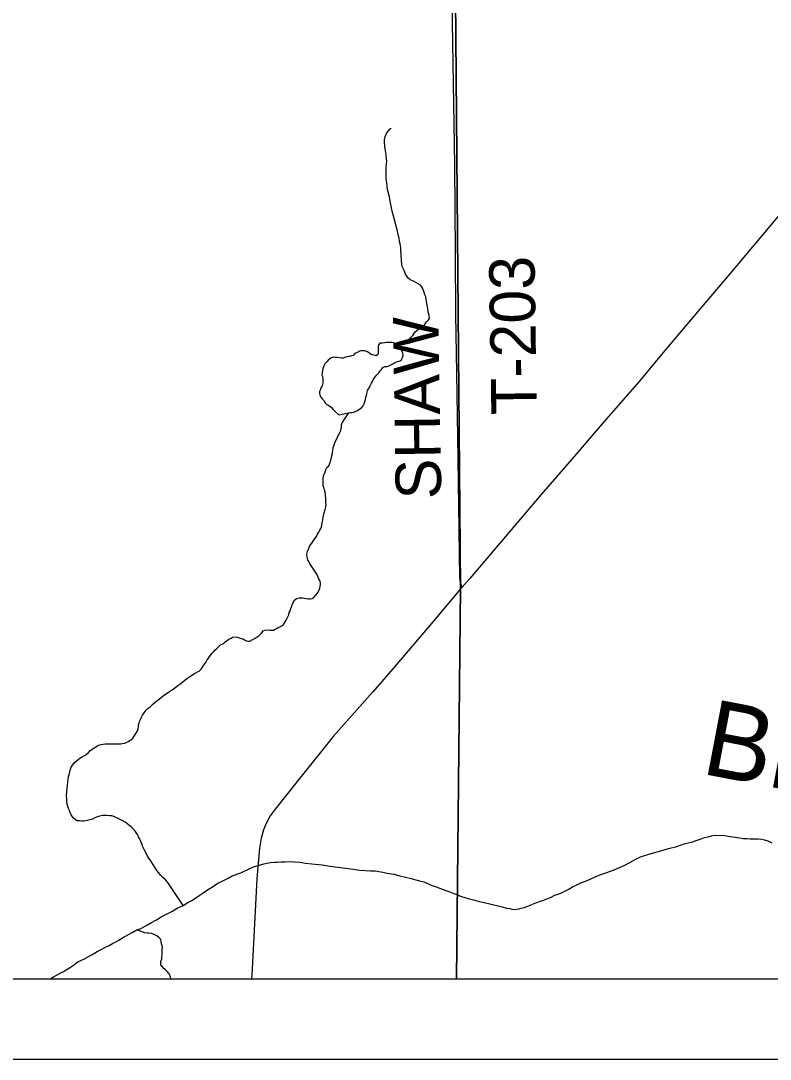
# Model space of a CAD drawing. Extents: x 0 to 34, y 0 to 22.
# Drawn here: x 3.905 to 4.841, y 14.238 to 15.535 of the extents above; entities that cross this region are included whole.
import ezdxf

# ---------------------------------------------------------------- set-up
doc = ezdxf.new("R2010")
doc.units = 0
for name, color, linetype in [('GM_X_County', 7, 'Continuous'), ('GM_X_Minor_Lake', 7, 'Continuous'), ('GM_X_Minor_River', 7, 'Continuous'), ('GM_X_Minor_River_Text', 7, 'Continuous'), ('GM_X_Township', 7, 'Continuous'), ('GM_X_Township_Road', 7, 'Continuous'), ('GM_X_Township_Road_Text', 7, 'Continuous'), ('SH_Data', 7, 'Continuous')]:
    doc.layers.add(name, color=color, linetype=linetype)

msp = doc.modelspace()

# ---------------------------------------------------------------- linework, layer by layer
at = {"layer": 'GM_X_County'}
msp.add_lwpolyline([(9.1622, 14.342), (9.1622, 21.1385), (2.3622, 21.1385), (2.3622, 14.3385), (9.0003, 14.3385)], dxfattribs=at)
at = {"layer": 'GM_X_Minor_Lake'}
for points in [[(4.3369, 15.0668), (4.3372, 15.0691), (4.3375, 15.0714), (4.3382, 15.0733), (4.3393, 15.0752), (4.3404, 15.0771), (4.3415, 15.0791), (4.3433, 15.0825), (4.3444, 15.0845), (4.3452, 15.0864), (4.347, 15.0891), (4.3492, 15.0922), (4.3522, 15.0953), (4.354, 15.0976), (4.3555, 15.0996), (4.357, 15.1015), (4.3596, 15.1031), (4.3623, 15.1031), (4.3645, 15.1036), (4.3672, 15.1051), (4.3706, 15.1071), (4.3732, 15.1087), (4.3762, 15.1095), (4.38, 15.1108), (4.3811, 15.1127), (4.3818, 15.1146), (4.3825, 15.1173), (4.3824, 15.12), (4.3816, 15.1218), (4.3808, 15.1241), (4.3796, 15.1267), (4.3776, 15.1297), (4.3757, 15.1308), (4.373, 15.1319), (4.3707, 15.1326), (4.3684, 15.133), (4.3658, 15.1333), (4.3639, 15.1332), (4.3616, 15.1332), (4.3597, 15.1328), (4.3567, 15.1323), (4.3536, 15.1322), (4.3518, 15.1303), (4.3514, 15.128), (4.3515, 15.1253), (4.3515, 15.1231), (4.3516, 15.1208), (4.3509, 15.1181), (4.349, 15.1165), (4.3463, 15.1172), (4.3441, 15.1176), (4.3421, 15.1187), (4.3394, 15.1205), (4.3371, 15.122), (4.3348, 15.1227), (4.3325, 15.1226), (4.3299, 15.1229), (4.328, 15.1225), (4.325, 15.1209), (4.3223, 15.1193), (4.3201, 15.117), (4.3182, 15.1166), (4.3156, 15.1158), (4.3129, 15.1153), (4.3106, 15.1149), (4.3076, 15.1137), (4.3057, 15.1136), (4.3027, 15.1139), (4.3, 15.1146), (4.2973, 15.1146), (4.295, 15.1149), (4.2928, 15.1141), (4.289, 15.1113), (4.2876, 15.1094), (4.2849, 15.1067), (4.2835, 15.104), (4.2824, 15.1005), (4.2817, 15.0986), (4.2814, 15.0956), (4.2811, 15.0925), (4.2819, 15.0906), (4.2823, 15.088), (4.2824, 15.0842), (4.2821, 15.0823), (4.2814, 15.0792), (4.2803, 15.0773), (4.2792, 15.0746), (4.2781, 15.0719), (4.2782, 15.07), (4.2786, 15.0674), (4.2802, 15.0647), (4.2814, 15.0628), (4.2837, 15.0606), (4.2853, 15.058), (4.2873, 15.0558), (4.2896, 15.0547), (4.2927, 15.0525), (4.2946, 15.0498), (4.2977, 15.0469), (4.3024, 15.0428), (4.3149, 15.0454)], [(4.3149, 15.0454), (4.3168, 15.0458), (4.3187, 15.0458), (4.321, 15.0463), (4.3228, 15.0471), (4.3255, 15.0483), (4.3285, 15.0502), (4.3307, 15.0518), (4.3326, 15.0541), (4.334, 15.0568), (4.3354, 15.0622), (4.3361, 15.0649), (4.3369, 15.0668)]]:
    msp.add_lwpolyline(points, dxfattribs=at)
at = {"layer": 'GM_X_Minor_River'}
for points in [[(4.3776, 15.1297), (4.3912, 15.138), (4.393, 15.1404), (4.3949, 15.1419), (4.3974, 15.1462), (4.3997, 15.1481), (4.4027, 15.1505), (4.4045, 15.152), (4.4072, 15.1536), (4.4101, 15.1567), (4.412, 15.1591), (4.4142, 15.1614), (4.4157, 15.1637), (4.4152, 15.1671), (4.4144, 15.1698), (4.414, 15.172), (4.4135, 15.1747), (4.4131, 15.1781), (4.4122, 15.1819), (4.4118, 15.1846), (4.4114, 15.1864), (4.4109, 15.1902), (4.4097, 15.1925), (4.4089, 15.1955), (4.408, 15.1982), (4.4068, 15.2012), (4.4056, 15.2031), (4.4045, 15.2049), (4.3956, 15.2097), (4.3933, 15.2108), (4.3914, 15.2115), (4.3887, 15.2141), (4.3871, 15.2159), (4.3855, 15.2186), (4.3843, 15.2224), (4.3827, 15.2257), (4.3815, 15.228), (4.381, 15.2314), (4.3806, 15.2344), (4.3805, 15.2375), (4.3801, 15.2405), (4.38, 15.2439), (4.3799, 15.247), (4.3799, 15.2489), (4.3798, 15.2512), (4.3794, 15.2538), (4.3789, 15.2565), (4.3781, 15.2595), (4.3776, 15.2633), (4.3764, 15.2678), (4.3755, 15.2724), (4.3734, 15.2799), (4.3714, 15.2879), (4.3689, 15.297), (4.3672, 15.3053), (4.3663, 15.3098), (4.3654, 15.3151), (4.3642, 15.3197), (4.3633, 15.3242), (4.3628, 15.3284), (4.3624, 15.3326), (4.3615, 15.3375), (4.3613, 15.3432), (4.3616, 15.3482), (4.3615, 15.352), (4.3618, 15.3558), (4.3621, 15.3596), (4.362, 15.3626), (4.3616, 15.3664), (4.3615, 15.3683), (4.3611, 15.3702), (4.3607, 15.3729), (4.3602, 15.3751), (4.3593, 15.3824), (4.3593, 15.3843), (4.3592, 15.3865), (4.3596, 15.3885), (4.3603, 15.3904), (4.3613, 15.3934), (4.3628, 15.3954), (4.3643, 15.3973), (4.3665, 15.4), (4.3676, 15.4008)], [(4.2774, 14.8234), (4.2784, 14.8265), (4.2791, 14.8288), (4.2795, 14.8311), (4.2794, 14.833), (4.279, 14.8349), (4.2782, 14.8368), (4.277, 14.839), (4.2762, 14.8409), (4.2746, 14.8439), (4.273, 14.8465), (4.2714, 14.8488), (4.2699, 14.8514), (4.2671, 14.8551), (4.2659, 14.8574), (4.2647, 14.8597), (4.2635, 14.8619), (4.2627, 14.8653), (4.2622, 14.8684), (4.2626, 14.8703), (4.2633, 14.8726), (4.2644, 14.8753), (4.2658, 14.8783), (4.2669, 14.8806), (4.2684, 14.8826), (4.2728, 14.8888), (4.2743, 14.8911), (4.2757, 14.8938), (4.2772, 14.8965), (4.2787, 14.8988), (4.2798, 14.9011), (4.2805, 14.903), (4.2812, 14.9049), (4.2815, 14.908), (4.2822, 14.9114), (4.2829, 14.9152), (4.2839, 14.9206), (4.2853, 14.9248), (4.286, 14.9279), (4.2863, 14.9309), (4.2862, 14.9336), (4.2862, 14.9363), (4.2861, 14.9389), (4.2857, 14.9416), (4.2856, 14.9435), (4.2852, 14.9461), (4.2844, 14.9491), (4.2839, 14.951), (4.2827, 14.9541), (4.2827, 14.9563), (4.2826, 14.959), (4.2826, 14.9609), (4.2825, 14.9628), (4.2832, 14.9666), (4.2846, 14.9705), (4.2861, 14.9743), (4.2879, 14.9774), (4.2898, 14.9793), (4.2912, 14.9824), (4.2919, 14.9851), (4.2926, 14.9878), (4.2933, 14.9901), (4.294, 14.9931), (4.2943, 14.9958), (4.2947, 14.9985), (4.2953, 15.0015), (4.2978, 15.0092), (4.2993, 15.0119), (4.3007, 15.015), (4.3015, 15.0169), (4.3026, 15.0188), (4.3037, 15.0207), (4.3047, 15.0234), (4.3054, 15.0273), (4.3057, 15.0303), (4.3064, 15.033), (4.3149, 15.0454)], [(4.0445, 14.6385), (4.0467, 14.6416), (4.0508, 14.6482), (4.0515, 14.6508), (4.0518, 14.6535), (4.0521, 14.6558), (4.0528, 14.6581), (4.0532, 14.66), (4.0543, 14.6623), (4.0553, 14.6646), (4.0568, 14.6677), (4.059, 14.6708), (4.0616, 14.6739), (4.0642, 14.6766), (4.0665, 14.6782), (4.0698, 14.6817), (4.0732, 14.6844), (4.0776, 14.688), (4.0829, 14.6919), (4.0896, 14.6966), (4.093, 14.699), (4.0964, 14.7013), (4.0997, 14.7041), (4.1035, 14.7064), (4.1072, 14.7096), (4.1124, 14.7135), (4.1173, 14.717), (4.1218, 14.7198), (4.1256, 14.7218), (4.1278, 14.723), (4.1304, 14.7253), (4.1319, 14.7276), (4.1337, 14.7307), (4.136, 14.7338), (4.1378, 14.7369), (4.1393, 14.7392), (4.1407, 14.7412), (4.1422, 14.7431), (4.1441, 14.7454), (4.1459, 14.7474), (4.1478, 14.7493), (4.15, 14.7513), (4.1519, 14.7532), (4.1545, 14.7555), (4.1575, 14.7571), (4.1601, 14.7595), (4.1631, 14.7614), (4.1657, 14.763), (4.1676, 14.7642), (4.1695, 14.7654), (4.1733, 14.7655), (4.1752, 14.7651), (4.1779, 14.7644), (4.1802, 14.7637), (4.1825, 14.763), (4.1844, 14.7619), (4.1867, 14.7608), (4.1886, 14.7601), (4.1909, 14.7602), (4.195, 14.7622), (4.1977, 14.7641), (4.2003, 14.7657), (4.2022, 14.7669), (4.204, 14.7685), (4.2055, 14.7704), (4.2077, 14.7731), (4.2096, 14.7739), (4.213, 14.7744), (4.2161, 14.7741), (4.2187, 14.7741), (4.2206, 14.7742), (4.2229, 14.7754), (4.2252, 14.7766), (4.2274, 14.7778), (4.2293, 14.7786), (4.2312, 14.7794), (4.233, 14.7809), (4.2352, 14.7844), (4.2363, 14.7863), (4.2374, 14.7883), (4.2385, 14.7906), (4.2396, 14.7933), (4.2403, 14.7959), (4.2414, 14.7982), (4.2421, 14.8009), (4.2453, 14.8086), (4.2468, 14.8113), (4.2494, 14.8136), (4.2528, 14.8145), (4.2551, 14.8145), (4.257, 14.8142), (4.2589, 14.8139), (4.2612, 14.8135), (4.2643, 14.8132), (4.2669, 14.8133), (4.2688, 14.8137), (4.2707, 14.8145), (4.2737, 14.8176), (4.2752, 14.8196), (4.2763, 14.8215), (4.2774, 14.8234)], [(4.1079, 14.4303), (4.0886, 14.4588), (4.0855, 14.4621), (4.0824, 14.4651), (4.0796, 14.4681), (4.0773, 14.4711), (4.0749, 14.4741), (4.0726, 14.4774), (4.0706, 14.4804), (4.0686, 14.4838), (4.0666, 14.4872), (4.0647, 14.4894), (4.0631, 14.492), (4.0619, 14.4947), (4.0595, 14.4992), (4.0583, 14.5018), (4.0571, 14.5045), (4.0563, 14.5067), (4.0551, 14.509), (4.0543, 14.5113), (4.0531, 14.5139), (4.0519, 14.5161), (4.0507, 14.5188), (4.0495, 14.5207), (4.0483, 14.5225), (4.0471, 14.5244), (4.0452, 14.5259), (4.0436, 14.5278), (4.0351, 14.5344), (4.0317, 14.5362), (4.029, 14.5377), (4.0263, 14.5388), (4.0236, 14.5402), (4.0209, 14.5413), (4.0186, 14.542), (4.0159, 14.5423), (4.0125, 14.5426), (4.0106, 14.5426), (4.0075, 14.5425), (4.0053, 14.5421), (4.0019, 14.5413), (3.9996, 14.5404), (3.9973, 14.5396), (3.9943, 14.538), (3.9894, 14.5368), (3.986, 14.5359), (3.9837, 14.5355), (3.9807, 14.5354), (3.978, 14.5358), (3.9753, 14.5361), (3.973, 14.5372), (3.9703, 14.5398), (3.9679, 14.5435), (3.9667, 14.5462), (3.9655, 14.5488), (3.9643, 14.5514), (3.9623, 14.5586), (3.9622, 14.5632), (3.9621, 14.5674), (3.9623, 14.5723), (3.9626, 14.5769), (3.9636, 14.5841), (3.9639, 14.5876), (3.9646, 14.591), (3.966, 14.5968), (3.9667, 14.5994), (3.9681, 14.6037), (3.9699, 14.606), (3.9714, 14.6083), (3.974, 14.6106), (3.9766, 14.6126), (3.9785, 14.6142), (3.9808, 14.6154), (3.983, 14.6169), (3.9853, 14.6177), (3.9871, 14.6193), (3.9894, 14.6213), (3.9916, 14.6236), (3.9942, 14.6256), (3.9965, 14.6271), (3.9987, 14.6283), (4.0006, 14.6295), (4.0032, 14.6307), (4.0051, 14.6311), (4.0078, 14.6316), (4.0104, 14.632), (4.0142, 14.6321), (4.018, 14.6322), (4.023, 14.6319), (4.0272, 14.632), (4.0298, 14.6321), (4.0317, 14.6325), (4.0348, 14.6329), (4.0367, 14.6338), (4.0385, 14.6346), (4.0427, 14.6373), (4.0445, 14.6385)], [(4.3523, 14.4728), (4.3573, 14.4718), (4.3627, 14.4707), (4.3711, 14.4694), (4.3783, 14.4673), (4.3856, 14.4656), (4.3925, 14.4638), (4.3986, 14.4624), (4.4032, 14.461), (4.4067, 14.4603), (4.4086, 14.4596), (4.4109, 14.4585), (4.4143, 14.4571), (4.4178, 14.4556), (4.4239, 14.4535), (4.4293, 14.4513), (4.4347, 14.4492), (4.4397, 14.4478), (4.4439, 14.446), (4.4485, 14.4442), (4.4543, 14.442), (4.4596, 14.4402), (4.4654, 14.4385), (4.4707, 14.4371), (4.4765, 14.4357), (4.4818, 14.4343), (4.4895, 14.4329), (4.5063, 14.4284), (4.5117, 14.427), (4.5159, 14.4263), (4.5186, 14.4256), (4.5216, 14.4253), (4.5239, 14.4257), (4.5273, 14.4262), (4.5303, 14.427), (4.5337, 14.4279), (4.5371, 14.4291), (4.5405, 14.4303), (4.5443, 14.4319), (4.5484, 14.4335), (4.553, 14.4351), (4.5579, 14.4368), (4.5624, 14.4384), (4.5669, 14.44), (4.5722, 14.4432), (4.5797, 14.4456), (4.5846, 14.448), (4.5895, 14.4508), (4.5944, 14.4536), (4.5997, 14.456), (4.6049, 14.4584), (4.6106, 14.4608), (4.6162, 14.4632), (4.6226, 14.466), (4.6298, 14.4689), (4.6374, 14.4713), (4.6464, 14.4749), (4.6532, 14.4778), (4.6596, 14.4806), (4.666, 14.4838), (4.6724, 14.4877), (4.6791, 14.4909), (4.6871, 14.4934), (4.6954, 14.4959), (4.7045, 14.4983), (4.7143, 14.5012), (4.7245, 14.5038), (4.7339, 14.5074), (4.7442, 14.5099), (4.7502, 14.5119), (4.7551, 14.5136), (4.7593, 14.5152), (4.7638, 14.5161), (4.768, 14.5173), (4.7717, 14.5182), (4.7847, 14.5177), (4.7912, 14.5163), (4.8011, 14.515), (4.8076, 14.514), (4.8126, 14.5138), (4.8164, 14.5135), (4.819, 14.5135), (4.8213, 14.5136), (4.8236, 14.5136), (4.8263, 14.5133), (4.8305, 14.513), (4.8343, 14.5124), (4.8385, 14.5109), (4.8435, 14.5084)], [(3.9419, 14.3385), (3.9456, 14.341), (3.9501, 14.3437), (3.9542, 14.3457), (3.958, 14.3477), (3.9617, 14.3497), (3.9658, 14.3525), (3.9707, 14.3556), (3.9763, 14.3599), (3.9846, 14.3636), (3.9902, 14.3671), (3.9955, 14.3699), (4.0004, 14.3727), (4.0053, 14.3754), (4.0098, 14.3778), (4.0151, 14.3802), (4.0196, 14.3826), (4.0237, 14.385), (4.0275, 14.387), (4.032, 14.3897), (4.0395, 14.3941), (4.0447, 14.3969), (4.05, 14.3997), (4.0549, 14.4017), (4.0594, 14.4041), (4.0632, 14.4061), (4.0681, 14.4088), (4.0737, 14.412), (4.0801, 14.416), (4.0868, 14.4192), (4.0936, 14.4227), (4.1004, 14.4267), (4.1079, 14.4303), (4.1135, 14.4338), (4.1192, 14.437), (4.1237, 14.4398), (4.1278, 14.4425), (4.1315, 14.4453), (4.1356, 14.448), (4.1401, 14.4512), (4.1458, 14.4544), (4.151, 14.4579), (4.1563, 14.4607), (4.1638, 14.4643), (4.1691, 14.4671), (4.1796, 14.4711), (4.1902, 14.4759), (4.1958, 14.4783), (4.203, 14.4804), (4.2068, 14.482), (4.2121, 14.4829), (4.2174, 14.4838), (4.2219, 14.4843), (4.2257, 14.4844), (4.2303, 14.4848), (4.2352, 14.4849), (4.2406, 14.4851), (4.2467, 14.4848), (4.2535, 14.4842), (4.2608, 14.4832), (4.2684, 14.4823), (4.2814, 14.4811), (4.2913, 14.4794), (4.3012, 14.4781), (4.3112, 14.4768), (4.3203, 14.4755), (4.3279, 14.4745), (4.3352, 14.4739), (4.342, 14.4737), (4.3478, 14.4734), (4.3523, 14.4728)], [(4.0926, 14.3385), (4.0925, 14.3386), (4.0921, 14.3405), (4.0916, 14.3424), (4.0901, 14.345), (4.0877, 14.348), (4.0858, 14.3499), (4.0838, 14.351), (4.0815, 14.354), (4.0799, 14.3562), (4.0798, 14.3593), (4.0802, 14.3615), (4.0809, 14.3635), (4.0812, 14.3669), (4.0815, 14.3688), (4.0815, 14.3707), (4.0814, 14.373), (4.0814, 14.3757), (4.0817, 14.3776), (4.0813, 14.3798), (4.0808, 14.3825), (4.0804, 14.3851), (4.0799, 14.3878), (4.0772, 14.3904), (4.0749, 14.3922), (4.073, 14.3933), (4.0707, 14.3944), (4.068, 14.3951), (4.0649, 14.3958), (4.0626, 14.3958), (4.06, 14.3961), (4.05, 14.3997)]]:
    msp.add_lwpolyline(points, dxfattribs=at)
at = {"layer": 'GM_X_Township'}
msp.add_line((4.4492, 14.3385), (9.0003, 14.3385), dxfattribs=at)
for points in [[(2.3622, 19.6335), (2.3622, 14.3385), (4.4492, 14.3385)], [(4.4492, 14.3385), (4.4543, 14.8268), (4.4378, 16.7908), (4.4338, 17.5835)], [(4.4338, 17.5835), (4.4378, 16.7908), (4.4543, 14.8268), (4.4492, 14.3385)]]:
    msp.add_lwpolyline(points, dxfattribs=at)
at = {"layer": 'GM_X_Township_Road'}
for points in [[(4.4562, 14.8276), (4.4543, 14.8329), (4.4533, 14.8395), (4.4515, 14.9883), (4.4499, 15.0947), (4.4483, 15.1681), (4.4481, 15.2446), (4.4472, 15.355), (4.4443, 15.5326), (4.4441, 15.5786), (4.4434, 15.7168), (4.4427, 16.092)], [(5.1078, 15.5882), (5.0494, 15.5193), (5.0175, 15.4818), (4.9971, 15.4592), (4.9467, 15.4036), (4.9296, 15.3831), (4.8694, 15.3122), (4.7909, 15.219), (4.7601, 15.1827), (4.7075, 15.1206), (4.6777, 15.0846), (4.6337, 15.0345), (4.594, 14.9881), (4.5552, 14.9434), (4.4659, 14.8386), (4.4562, 14.8276)], [(4.4562, 14.8276), (4.4543, 14.8254), (4.4228, 14.7878), (4.3671, 14.723), (4.3447, 14.6972), (4.2957, 14.6415), (4.2504, 14.5852), (4.2226, 14.5504), (4.2165, 14.5421), (4.2113, 14.5324), (4.2082, 14.5248), (4.2053, 14.5142), (4.2033, 14.5017), (4.1999, 14.4637), (4.1934, 14.3432), (4.1932, 14.3385)]]:
    msp.add_lwpolyline(points, dxfattribs=at)
at = {"layer": 'SH_Data'}
msp.add_line((2.2617, 14.2383), (9.2617, 14.2383), dxfattribs=at)

# ---------------------------------------------------------------- texts
at = {"layer": 'GM_X_Minor_River_Text'}
msp.add_text('Brook', height=0.09475, rotation=349.2053, dxfattribs=at).set_placement((4.7532, 14.5952))
at = {"layer": 'GM_X_Township_Road_Text'}
for s, rotation, p in [('T-203', 90.846, (4.5497, 15.0432)), ('SHAW', 90.9362, (4.4304, 14.9378))]:
    msp.add_text(s, height=0.05682, rotation=rotation, dxfattribs=at).set_placement(p)

doc.saveas('drawing.dxf')
